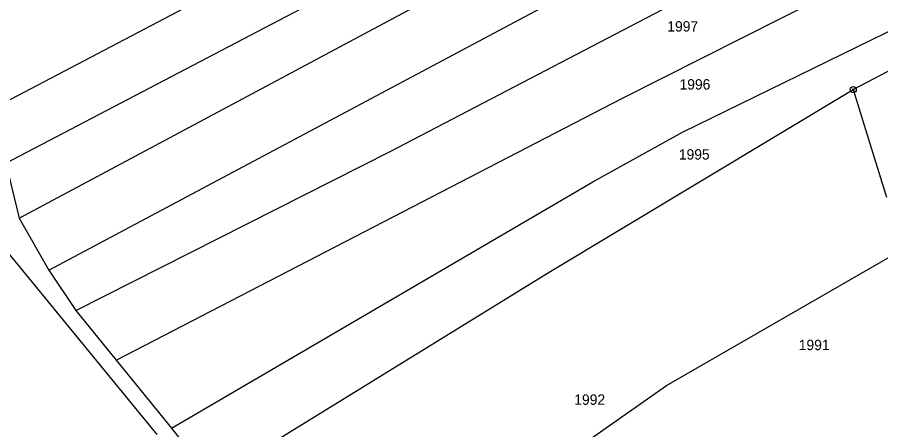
# Model space of a CAD drawing. Extents: x -763205 to -760228, y -1155311 to -1152844.
# Drawn here: x -761715.4 to -761573.8, y -1154484.3 to -1154416.7 of the extents above; entities that cross this region are included whole.
import ezdxf

# ---------------------------------------------------------------- set-up
doc = ezdxf.new("R2010")
doc.units = 0
for name, color, linetype in [('Vrstva 1', 7, 'Continuous'), ('Vrstva 18', 7, 'Continuous'), ('Vrstva 24', 7, 'Continuous'), ('Vrstva 6', 7, 'Continuous')]:
    doc.layers.add(name, color=color, linetype=linetype)

msp = doc.modelspace()

# ---------------------------------------------------------------- linework, layer by layer
at = {"layer": 'Vrstva 1'}
for p, q in [((-761578.33, -1154428.54), (-761566.76, -1154422.44)), ((-761578.33, -1154428.54), (-761575.61, -1154437.36)), ((-761575.61, -1154437.36), (-761572.9, -1154446.15)), ((-761717.74, -1154454.29), (-761692.49, -1154485.08))]:
    msp.add_line(p, q, dxfattribs=at)
at = {"layer": 'Vrstva 24'}
for radius in [0.5, 0.1]:
    msp.add_circle((-761578.33, -1154428.54), radius, dxfattribs=at)
at = {"layer": 'Vrstva 6'}
for p, q in [((-761717.26, -1154440.59), (-761636.18, -1154398.17)), ((-761654.23, -1154438.67), (-761588, -1154404.1)), ((-761720.75, -1154432.39), (-761670.91, -1154406.18)), ((-761606.34, -1154435.54), (-761546.43, -1154406.25)), ((-761715.05, -1154449.62), (-761635.1, -1154406.86)), ((-761616.16, -1154429.95), (-761574.76, -1154409.04)), ((-761710.22, -1154458.15), (-761624.9, -1154412.67)), ((-761628.48, -1154458.64), (-761578.33, -1154428.54)), ((-761699.15, -1154472.91), (-761616.16, -1154429.95)), ((-761621.05, -1154443.69), (-761606.34, -1154435.54)), ((-761705.78, -1154464.74), (-761654.23, -1154438.67)), ((-761717.26, -1154440.59), (-761715.05, -1154449.62)), ((-761690.11, -1154484.04), (-761621.05, -1154443.69)), ((-761715.05, -1154449.62), (-761710.22, -1154458.15)), ((-761608.96, -1154477.08), (-761570.25, -1154454.72)), ((-761710.22, -1154458.15), (-761705.78, -1154464.74)), ((-761683.46, -1154492.5), (-761628.48, -1154458.64)), ((-761705.78, -1154464.74), (-761699.15, -1154472.91)), ((-761699.15, -1154472.91), (-761690.11, -1154484.04)), ((-761633.85, -1154494.49), (-761608.96, -1154477.08)), ((-761690.11, -1154484.04), (-761683.46, -1154492.5))]:
    msp.add_line(p, q, dxfattribs=at)

# ---------------------------------------------------------------- texts
at = {"layer": 'Vrstva 18'}
for s, p in [('1997', (-761608.817, -1154419.02)), ('1996', (-761606.817, -1154428.53)), ('1995', (-761606.927, -1154440.01)), ('1991', (-761587.267, -1154471.26)), ('1992', (-761624.067, -1154480.22))]:
    msp.add_text(s, height=1.7, dxfattribs=at).set_placement(p)

doc.saveas('drawing.dxf')
